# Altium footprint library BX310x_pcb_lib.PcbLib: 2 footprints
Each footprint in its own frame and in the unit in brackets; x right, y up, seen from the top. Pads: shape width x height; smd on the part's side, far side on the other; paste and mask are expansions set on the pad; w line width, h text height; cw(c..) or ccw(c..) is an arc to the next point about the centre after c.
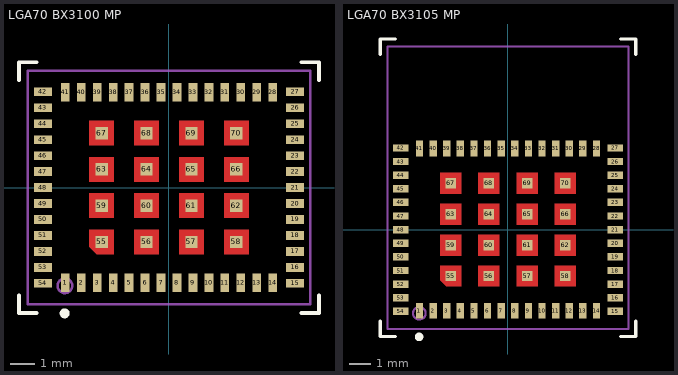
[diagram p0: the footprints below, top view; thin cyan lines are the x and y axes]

## LGA70 BX3100 MP [mm] "LGA, 70-Leads, Body 9.5x11.5mm, Pitch 0.65mm"
height 2.4
pads (70):
  rect 0.35x0.75 smd mask+0.05: 1(-4.225,-3.875) 2(-3.575,-3.875) 3(-2.925,-3.875) 4(-2.275,-3.875) 5(-1.625,-3.875) 6(-0.975,-3.875) 7(-0.325,-3.875) 8(0.325,-3.875) 9(0.975,-3.875) 10(1.625,-3.875) 11(2.275,-3.875) 12(2.925,-3.875) 13(3.575,-3.875) 14(4.225,-3.875) 28(4.225,3.875) 29(3.575,3.875) 30(2.925,3.875) 31(2.275,3.875) 32(1.625,3.875) 33(0.975,3.875) 34(0.325,3.875) 35(-0.325,3.875) 36(-0.975,3.875) 37(-1.625,3.875) 38(-2.275,3.875) 39(-2.925,3.875) 40(-3.575,3.875) 41(-4.225,3.875)
  rect 0.75x0.35 smd mask+0.05: 15(5.125,-3.9) 16(5.125,-3.25) 17(5.125,-2.6) 18(5.125,-1.95) 21(5.125,0) 22(5.125,0.65) 23(5.125,1.3) 24(5.125,1.95) 25(5.125,2.6) 26(5.125,3.25) 27(5.125,3.9) 42(-5.125,3.9) 43(-5.125,3.25) 44(-5.125,2.6) 45(-5.125,1.95) 46(-5.125,1.3) 47(-5.125,0.65) 48(-5.125,0) 49(-5.125,-0.65) 50(-5.125,-1.3) 51(-5.125,-1.95) 52(-5.125,-2.6) 53(-5.125,-3.25) 54(-5.125,-3.9)
  rect 0.75x0.35 smd paste+0 mask+0.05: 19(5.125,-1.3) 20(5.125,-0.65)
  rect 0.5x0.5 smd paste-0.5 mask-0.5: 55(-2.738,-2.212) 56(-0.912,-2.213) 57(0.913,-2.213) 58(2.738,-2.213) 59(-2.738,-0.738) 60(-0.913,-0.738) 61(0.912,-0.738) 62(2.737,-0.738) 63(-2.738,0.737) 64(-0.913,0.737) 65(0.912,0.737) 66(2.737,0.737) 67(-2.738,2.213) 68(-0.913,2.213) 69(0.912,2.213) 70(2.737,2.213)
Top Layer:
  region: -3.238,-1.713 -2.238,-1.713 -2.238,-2.712 -2.938,-2.712 -3.238,-2.412
  region: -3.238,2.712 -2.238,2.712 -2.238,1.712 -3.238,1.712
  region: -1.413,2.712 -0.413,2.712 -0.413,1.712 -1.413,1.712
  region: 0.412,2.712 1.412,2.712 1.412,1.712 0.412,1.712
  region: 2.237,2.712 3.237,2.712 3.237,1.712 2.237,1.712
  region: -3.238,1.236 -2.238,1.236 -2.238,0.236 -3.238,0.236
  region: -1.413,1.236 -0.413,1.236 -0.413,0.236 -1.413,0.236
  region: 0.412,1.236 1.412,1.236 1.412,0.236 0.412,0.236
  region: 2.237,1.236 3.237,1.236 3.237,0.236 2.237,0.236
  region: 2.237,-0.239 3.237,-0.239 3.237,-1.239 2.237,-1.239
  region: 0.412,-0.239 1.412,-0.239 1.412,-1.239 0.412,-1.239
  region: -1.413,-0.239 -0.413,-0.239 -0.413,-1.239 -1.413,-1.239
  region: -3.238,-0.239 -2.238,-0.239 -2.238,-1.239 -3.238,-1.239
  region: -1.412,-1.713 -0.412,-1.713 -0.412,-2.713 -1.412,-2.713
  region: 0.412,-1.713 1.412,-1.713 1.412,-2.713 0.412,-2.713
  region: 2.237,-1.713 3.237,-1.713 3.237,-2.713 2.237,-2.713
Top Overlay:
  circle w0.2: c-4.243,-5.118 r0.102
  lines w0.15: -6.1,-4.375 -6.1,-5.1 -5.375,-5.1 ; -6.1,4.375 -6.1,5.1 -5.375,5.1 ; 5.375,-5.1 6.1,-5.1 6.1,-4.375 ; 5.375,5.1 6.1,5.1 6.1,4.375
Top Paste:
  drawing of 48 lines, arcs and shapes, not listed
Top Solder:
  region: -3.288,2.762 -2.188,2.762 -2.188,1.662 -3.288,1.662
  region: -1.463,2.762 -0.363,2.762 -0.363,1.662 -1.463,1.662
  region: 0.362,2.762 1.462,2.762 1.462,1.662 0.362,1.662
  region: 2.187,2.762 3.287,2.762 3.287,1.662 2.187,1.662
  region: -3.288,1.286 -2.188,1.286 -2.188,0.186 -3.288,0.186
  region: -1.463,1.286 -0.363,1.286 -0.363,0.186 -1.463,0.186
  region: 0.362,1.286 1.462,1.286 1.462,0.186 0.362,0.186
  region: 2.187,1.286 3.287,1.286 3.287,0.186 2.187,0.186
  region: 2.187,-0.189 3.287,-0.189 3.287,-1.289 2.187,-1.289
  region: 0.362,-0.189 1.462,-0.189 1.462,-1.289 0.362,-1.289
  region: -1.463,-0.189 -0.363,-0.189 -0.363,-1.289 -1.463,-1.289
  region: -3.288,-0.189 -2.188,-0.189 -2.188,-1.289 -3.288,-1.289
  region: -1.462,-1.663 -0.362,-1.663 -0.362,-2.763 -1.462,-2.763
  region: 0.362,-1.663 1.462,-1.663 1.462,-2.763 0.362,-2.763
  region: 2.187,-1.663 3.287,-1.663 3.287,-2.763 2.187,-2.763
  region: -3.288,-1.663 -2.188,-1.663 -2.188,-2.762 -2.987,-2.762 -3.288,-2.463
Mechanical 4:
  circle w0.1: c-4.233,-3.992 r0.3
  lines w0.1: -5.75,-4.75 5.75,-4.75 5.75,4.75 -5.75,4.75 -5.75,-4.75
  text ".Designator" at 0,0 h0.4
3D body: height 2.4, standoff 1.1, extent -5.3,-4.3 5.3,4.3
3D body: height 1.1, standoff 0, extent -5.75,-4.75 5.75,4.75

## LGA70 BX3105 MP [mm] "LGA, 70-Leads, Body 13.5x11.5mm, Pitch 0.65mm"
height 2.4
pads (70):
  rect 0.35x0.75 smd mask+0.05: 1(-4.225,-3.875) 2(-3.575,-3.875) 3(-2.925,-3.875) 4(-2.275,-3.875) 5(-1.625,-3.875) 6(-0.975,-3.875) 7(-0.325,-3.875) 8(0.325,-3.875) 9(0.975,-3.875) 10(1.625,-3.875) 11(2.275,-3.875) 12(2.925,-3.875) 13(3.575,-3.875) 14(4.225,-3.875) 28(4.225,3.875) 29(3.575,3.875) 30(2.925,3.875) 31(2.275,3.875) 32(1.625,3.875) 33(0.975,3.875) 34(0.325,3.875) 35(-0.325,3.875) 36(-0.975,3.875) 37(-1.625,3.875) 38(-2.275,3.875) 39(-2.925,3.875) 40(-3.575,3.875) 41(-4.225,3.875)
  rect 0.75x0.35 smd mask+0.05: 15(5.125,-3.9) 16(5.125,-3.25) 17(5.125,-2.6) 18(5.125,-1.95) 19(5.125,-1.3) 20(5.125,-0.65) 21(5.125,0) 22(5.125,0.65) 23(5.125,1.3) 24(5.125,1.95) 25(5.125,2.6) 26(5.125,3.25) 27(5.125,3.9) 42(-5.125,3.9) 43(-5.125,3.25) 44(-5.125,2.6) 45(-5.125,1.95) 46(-5.125,1.3) 47(-5.125,0.65) 48(-5.125,0) 49(-5.125,-0.65) 50(-5.125,-1.3) 51(-5.125,-1.95) 52(-5.125,-2.6) 53(-5.125,-3.25) 54(-5.125,-3.9)
  rect 0.5x0.5 smd paste-0.5 mask-0.5: 55(-2.738,-2.212) 56(-0.912,-2.213) 57(0.913,-2.213) 58(2.738,-2.213) 59(-2.738,-0.738) 60(-0.913,-0.738) 61(0.912,-0.738) 62(2.737,-0.738) 63(-2.738,0.737) 64(-0.913,0.737) 65(0.912,0.737) 66(2.737,0.737) 67(-2.738,2.213) 68(-0.913,2.213) 69(0.912,2.213) 70(2.737,2.213)
Top Layer:
  region: -3.238,-1.713 -2.238,-1.713 -2.238,-2.712 -2.938,-2.712 -3.238,-2.412
  region: -3.238,2.712 -2.238,2.712 -2.238,1.712 -3.238,1.712
  region: -1.413,2.712 -0.413,2.712 -0.413,1.712 -1.413,1.712
  region: 0.412,2.712 1.412,2.712 1.412,1.712 0.412,1.712
  region: 2.237,2.712 3.237,2.712 3.237,1.712 2.237,1.712
  region: -3.238,1.236 -2.238,1.236 -2.238,0.236 -3.238,0.236
  region: -1.413,1.236 -0.413,1.236 -0.413,0.236 -1.413,0.236
  region: 0.412,1.236 1.412,1.236 1.412,0.236 0.412,0.236
  region: 2.237,1.236 3.237,1.236 3.237,0.236 2.237,0.236
  region: 2.237,-0.239 3.237,-0.239 3.237,-1.239 2.237,-1.239
  region: 0.412,-0.239 1.412,-0.239 1.412,-1.239 0.412,-1.239
  region: -1.413,-0.239 -0.413,-0.239 -0.413,-1.239 -1.413,-1.239
  region: -3.238,-0.239 -2.238,-0.239 -2.238,-1.239 -3.238,-1.239
  region: -1.412,-1.713 -0.412,-1.713 -0.412,-2.713 -1.412,-2.713
  region: 0.412,-1.713 1.412,-1.713 1.412,-2.713 0.412,-2.713
  region: 2.237,-1.713 3.237,-1.713 3.237,-2.713 2.237,-2.713
Top Overlay:
  circle w0.2: c-4.243,-5.118 r0.102
  lines w0.15: -6.1,-4.375 -6.1,-5.1 -5.375,-5.1 ; -6.1,8.375 -6.1,9.1 -5.375,9.1 ; 5.375,-5.1 6.1,-5.1 6.1,-4.375 ; 5.375,9.1 6.1,9.1 6.1,8.375
Top Paste:
  drawing of 48 lines, arcs and shapes, not listed
Top Solder:
  region: -3.288,2.762 -2.188,2.762 -2.188,1.662 -3.288,1.662
  region: -1.463,2.762 -0.363,2.762 -0.363,1.662 -1.463,1.662
  region: 0.362,2.762 1.462,2.762 1.462,1.662 0.362,1.662
  region: 2.187,2.762 3.287,2.762 3.287,1.662 2.187,1.662
  region: -3.288,1.286 -2.188,1.286 -2.188,0.186 -3.288,0.186
  region: -1.463,1.286 -0.363,1.286 -0.363,0.186 -1.463,0.186
  region: 0.362,1.286 1.462,1.286 1.462,0.186 0.362,0.186
  region: 2.187,1.286 3.287,1.286 3.287,0.186 2.187,0.186
  region: 2.187,-0.189 3.287,-0.189 3.287,-1.289 2.187,-1.289
  region: 0.362,-0.189 1.462,-0.189 1.462,-1.289 0.362,-1.289
  region: -1.463,-0.189 -0.363,-0.189 -0.363,-1.289 -1.463,-1.289
  region: -3.288,-0.189 -2.188,-0.189 -2.188,-1.289 -3.288,-1.289
  region: -1.462,-1.663 -0.362,-1.663 -0.362,-2.763 -1.462,-2.763
  region: 0.362,-1.663 1.462,-1.663 1.462,-2.763 0.362,-2.763
  region: 2.187,-1.663 3.287,-1.663 3.287,-2.763 2.187,-2.763
  region: -3.288,-1.663 -2.188,-1.663 -2.188,-2.762 -2.987,-2.762 -3.288,-2.463
Mechanical 4:
  circle w0.1: c-4.233,-3.992 r0.3
  lines w0.1: -5.75,-4.75 5.75,-4.75 5.75,8.75 -5.75,8.75 -5.75,-4.75
  text ".Designator" at 0,0 h0.4
3D body: height 1.1, standoff 0, extent -5.75,-4.75 5.75,8.75
3D body: height 2.4, standoff 1.1, extent -5.3,-4.3 5.3,4.3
